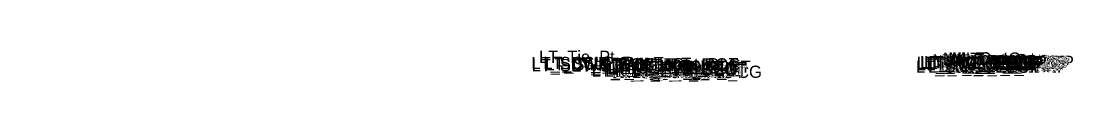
# Model space of a CAD drawing. Extents: x 0 to 4229, y -1 to 9523.
# Drawn here: x 3000 to 3171.5, y 2000 to 2005.9 of the extents above; entities that cross this region are included whole.
import ezdxf

# ---------------------------------------------------------------- set-up
doc = ezdxf.new("R2010")
doc.units = 0
doc.layers.add('Default', color=7, linetype='Continuous')

msp = doc.modelspace()

# ---------------------------------------------------------------- texts
at = {"layer": 'Default'}
for s, height, p in [('LT_Tie_Pt', 2, (3084.47, 2003.76)), ('MI_Top In', 2, (3150.36, 2003.44)), ('MI_Top Out', 2, (3151.22, 2003.48)), ('MI_Crown', 2, (3151.82, 2003.51)), ('LT_SDWK_Out_Top', 2, (3083.24, 2002.75)), ('LT_SDWK_Out_Bot', 2, (3083.27, 2002.41)), ('LT_CSLP_Pnt', 2, (3085.17, 2002.77)), ('LT_Sub_Trench_Out_DLT', 2, (3085.49, 2002.57)), ('LT_SDWK_In_Top', 2, (3089.86, 2002.65)), ('LT_SDWK_In_Bot', 2, (3089.89, 2002.31)), ('LT_CG_Top_Face', 2, (3094.76, 2002.53)), ('LT_CG_Top_BOC', 2, (3095.28, 2002.53)), ('LT_CG_Top_Gut', 2, (3095.74, 2002.03)), ('LT_PV2_OEOT', 2, (3099.67, 2001.9)), ('LT_PV3_OEOT', 2, (3099.67, 2001.65)), ('LT_PV1_OEOT', 2, (3100.24, 2002.15)), ('LT_Sub_OEEOP', 2, (3145.96, 2002.15)), ('LT_PV2_OEEOP', 2, (3146.06, 2002.78)), ('LT_PV3_OEEOP', 2, (3146.06, 2002.53)), ('LT_PV1_OEEOP', 2, (3146.62, 2002.9)), ('LT_PV2_IEEOP', 2, (3146.7, 2002.78)), ('LT_PV1_IEEOP', 2, (3147.27, 2002.9)), ('LT_PV2_PGL1', 2, (3147.63, 2002.78)), ('LT_PV3_PGL1', 2, (3147.63, 2002.53)), ('LT_PV2_PGL', 2, (3147.96, 2002.78)), ('LT_PV4_PGL', 2, (3147.96, 2002.15)), ('LT_PV1_PGL', 2, (3148.53, 2003.03)), ('MI_Face In', 2, (3148.65, 2003.19)), ('MI_Bot In', 2, (3149.63, 2003.03)), ('RT_Sub_OEEOP', 2, (3149.92, 2002.19)), ('RT_PV2_OEEOP', 2, (3150.01, 2002.82)), ('RT_PV3_OEEOP', 2, (3150.01, 2002.57)), ('RT_PV1_OEEOP', 2, (3150.58, 2002.94)), ('RT_PV2_IEEOP', 2, (3150.66, 2002.82)), ('MI_Face Out', 2, (3151.01, 2003.23)), ('RT_PV1_IEEOP', 2, (3151.22, 2002.94)), ('RT_PV2_PGL1', 2, (3151.58, 2002.82)), ('RT_PV3_PGL1', 2, (3151.58, 2002.57)), ('RT_PV2_PGL', 2, (3151.92, 2002.82)), ('RT_PV4_PGL', 2, (3151.92, 2002.19)), ('MI_Bot Out', 2, (3152.01, 2003.07)), ('RT_PV1_PGL', 2, (3152.48, 2003.07)), ('LT_CG1_Shelf_Out', 2, (3093.05, 2001.51)), ('LT_CG_Bot_BOC', 2, (3095.31, 2001.52)), ('LT_Sub_OEOP', 2, (3096.36, 2001.25)), ('LT_Sub_OEOT_CG', 2, (3096.87, 2001.32)), ('LT_CG_Bot_IE', 2, (3099.41, 2001.57)), ('LT_Sub_OEOT', 2, (3099.58, 2001.28)), ('-', 0.0001, (3000, 2000)), ('-', 0.0001, (3000, 2000)), ('-', 0.0001, (3000, 2000)), ('-', 0.0001, (3000, 2000)), ('-', 0.0001, (3000, 2000)), ('-', 0.0001, (3000, 2000)), ('-', 0.0001, (3000, 2000))]:
    msp.add_text(s, height=height, dxfattribs=at).set_placement(p)

doc.saveas('drawing.dxf')
